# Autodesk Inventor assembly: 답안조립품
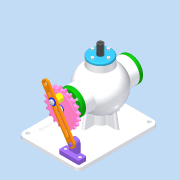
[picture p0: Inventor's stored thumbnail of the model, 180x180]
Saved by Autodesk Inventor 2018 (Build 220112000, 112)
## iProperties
Created: 2022-09
Part Number: 답안조립품
Material: 일반
Document SubType Name: Assembly
Designer: home
Author: home
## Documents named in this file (20)
- C:\Users\kimgi\Desktop\620906V1007\답안조립품.iam
- C:\Users\kimgi\Desktop\620906V1007\본체.ipt
- C:\Users\kimgi\Desktop\620906V1007\본체커버.ipt
- C:\Users\kimgi\Desktop\620906V1007\앞커버.ipt
- C:\Users\kimgi\Desktop\620906V1007\뒤커버.ipt
- C:\Users\kimgi\Desktop\620906V1007\볼트 M4x12.ipt
- C:\Users\kimgi\Desktop\620906V1007\슬라이드 커버.ipt
- C:\Users\kimgi\Desktop\620906V1007\베어링 6202.ipt
- C:\Users\kimgi\Desktop\620906V1007\오일실.ipt
- C:\Users\kimgi\Desktop\620906V1007\축.ipt
- C:\Users\kimgi\Desktop\620906V1007\키 3x3.ipt
- C:\Users\kimgi\Desktop\620906V1007\스프로킷.ipt
- C:\Users\kimgi\Desktop\620906V1007\와셔 8x17.ipt
- C:\Users\kimgi\Desktop\620906V1007\너트 M8x1.ipt
- C:\Users\kimgi\Desktop\620906V1007\힌지.ipt
- C:\Users\kimgi\Desktop\620906V1007\커넥트 암.ipt
- C:\Users\kimgi\Desktop\620906V1007\칼라.ipt
- C:\Users\kimgi\Desktop\620906V1007\연결 핀.ipt
- C:\Users\kimgi\Desktop\620906V1007\가변스프링.ipt
- C:\Users\kimgi\Desktop\620906V1007\슬라이드.ipt
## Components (1 placed, 1 different names)
1. 가변스프링:1
